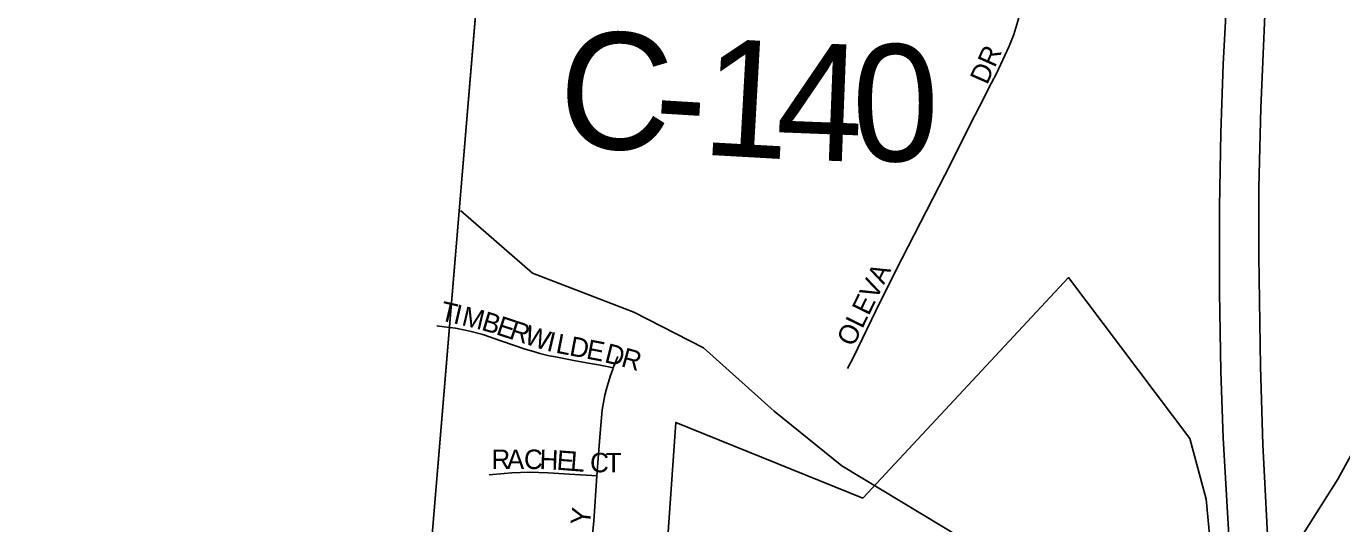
# Model space of a CAD drawing. Extents: x 1410790 to 1770854, y 448063 to 770588.
# Drawn here: x 1515012 to 1518387, y 615308 to 616585 of the extents above; entities that cross this region are included whole.
import ezdxf

# ---------------------------------------------------------------- set-up
doc = ezdxf.new("R2010")
doc.units = 0
for name, color, linetype in [('GM_X_Adjacent_County', 7, 'Continuous'), ('GM_X_Corporation', 7, 'Continuous'), ('GM_X_County', 7, 'Continuous'), ('GM_X_County_Road_Text', 7, 'Continuous'), ('GM_X_Interstate_Route', 7, 'Continuous'), ('GM_X_Minor_River', 7, 'Continuous'), ('GM_X_Township', 7, 'Continuous'), ('GM_X_Township_Subdivision', 7, 'Continuous'), ('GM_X_Township_Subdivision_Text', 7, 'Continuous')]:
    doc.layers.add(name, color=color, linetype=linetype)

msp = doc.modelspace()

# ---------------------------------------------------------------- linework, layer by layer
at = {"layer": 'GM_X_Adjacent_County'}
msp.add_lwpolyline([(1516461.1, 620230.1), (1516373.4, 619132.2), (1516259.6, 617762.4), (1516179.6, 616799.3), (1516178.5, 616785.8), (1516097.7, 615813.6), (1515954.1, 614086), (1515919.3, 613667.1), (1515731.8, 611411.8), (1515651.7, 611077.8), (1515518.3, 609565), (1515445.2, 608706.8), (1515408.7, 608098.4), (1515389.4, 607781.4), (1515371.9, 607595.9), (1515366.2, 607536), (1515338.7, 607244), (1515313.5, 606977), (1515267.7, 606491.6), (1515138.6, 605013.3), (1515011.7, 603538)], dxfattribs=at)
at = {"layer": 'GM_X_Corporation'}
msp.add_lwpolyline([(1516179.5, 616799.3), (1515953.4, 614078.9), (1516560, 613881.8), (1516677.9, 615567.6), (1517158.2, 615373.6), (1517686.1, 615939.7), (1517997.2, 615526.8), (1518038.9, 615370.3), (1518120.4, 614509.1), (1518162.4, 613531.2), (1518064.1, 613491.5), (1517980.9, 613509.2), (1517500.9, 613655.9), (1517499.1, 613630), (1517272.7, 613703.6), (1517210.9, 613723.6), (1517196.3, 613675.8), (1517284.6, 613626.9), (1518220.1, 613267.8), (1518169.3, 613029.1)], dxfattribs=at)
at = {"layer": 'GM_X_County'}
msp.add_lwpolyline([(1516461.1, 620230.1), (1516373.4, 619132.2), (1516259.6, 617762.4), (1516179.6, 616799.3), (1516178.5, 616785.8), (1516097.7, 615813.6), (1515954.1, 614086), (1515919.3, 613667.1), (1515731.8, 611411.8), (1515651.7, 611077.8), (1515518.3, 609565), (1515445.2, 608706.8), (1515408.7, 608098.4), (1515389.4, 607781.4), (1515371.9, 607595.9), (1515366.2, 607536), (1515338.7, 607244), (1515313.5, 606977), (1515267.7, 606491.6), (1515138.6, 605013.3), (1515011.7, 603538)], dxfattribs=at)
at = {"layer": 'GM_X_Interstate_Route'}
for points in [[(1518369.1, 611170.7), (1518352.1, 611439.2), (1518313.6, 612028.4), (1518281.4, 612490), (1518248.2, 612990.8), (1518240, 613108.7), (1518234, 613197), (1518223.3, 613372.3), (1518218.2, 613455.6), (1518188.2, 613894.3), (1518163, 614290.4), (1518139.7, 614644.1), (1518119.7, 614928.9), (1518097.8, 615262.7), (1518082.9, 615527.8), (1518077, 615698.1), (1518073.2, 615901.3), (1518073.1, 616120.9), (1518076.7, 616311), (1518082.9, 616487.8), (1518096.8, 616755.9)], [(1518478.2, 611056.4), (1518460.5, 611318.1), (1518429.3, 611763.2), (1518403, 612195.4), (1518389.4, 612391.7), (1518384.3, 612463.7), (1518353.9, 612908.8), (1518335.5, 613183.7), (1518325.6, 613340.9), (1518321.3, 613409.6), (1518275.5, 614090.4), (1518241.7, 614604.3), (1518213, 615019.9), (1518195.7, 615295), (1518184.5, 615511.4), (1518178.2, 615711.5), (1518174, 615993.7), (1518174.3, 616171), (1518178.9, 616374.6), (1518195.7, 616753.6)]]:
    msp.add_lwpolyline(points, dxfattribs=at)
at = {"layer": 'GM_X_Minor_River'}
for points in [[(1517975.9, 614867.7), (1518203.6, 615147.1), (1518377.1, 615422.3), (1518541.1, 615721.8), (1518584.2, 615777.1), (1518902.1, 615958.9), (1519075.7, 616129.7), (1519158.2, 616256.4), (1519264.5, 616370.5), (1519357.8, 616430.7), (1519412.2, 616447.6), (1519854, 616506.3), (1520047.6, 616574.3), (1520264, 616684)], [(1518568.9, 613289), (1518509.3, 613326.5), (1518484.3, 613381.2), (1518386.3, 613493.7), (1518369.5, 613560.2), (1518432.5, 613813.7), (1518418.9, 613940.4), (1518341, 614162.8), (1518345.2, 614275.1), (1518281.2, 614384.9), (1518226.6, 614568.7), (1518166.8, 614690.4), (1518054.1, 614765), (1517925.1, 614934.4), (1517873.5, 614955.6), (1517805.9, 614983.2), (1517689, 615049.9), (1517460.3, 615241.5), (1517103.9, 615456), (1516930.3, 615596.3), (1516749.2, 615758.8), (1516570.7, 615851), (1516310.2, 615951), (1516125.4, 616111.9)]]:
    msp.add_lwpolyline(points, dxfattribs=at)
at = {"layer": 'GM_X_Township'}
msp.add_lwpolyline([(1515651.7, 611077.8), (1515731.8, 611411.8), (1515919.3, 613667.1), (1515954.1, 614086), (1516097.7, 615813.6), (1516178.5, 616785.8), (1516179.6, 616799.3), (1516487.5, 616797.3), (1516773.1, 616795.4), (1517166.1, 616772.8), (1517456.2, 616756.2), (1517607.5, 616751.1), (1518142.2, 616733), (1518385.8, 616724.8), (1518670.6, 616715.2), (1522108.4, 616599.1), (1522130.9, 616592.7), (1524051.6, 616052.7), (1524353.6, 615961.7), (1525559.8, 615628.7)], dxfattribs=at)
at = {"layer": 'GM_X_Township_Subdivision'}
for points in [[(1517118.6, 615705.9), (1517134.2, 615735), (1517191.3, 615854.4), (1517226.4, 615925.1), (1517258.3, 615987.9), (1517306.3, 616080.7), (1517384.1, 616232.8), (1517412.9, 616291.6), (1517445.8, 616355.7), (1517457.7, 616379), (1517488, 616439.3), (1517501, 616463.9), (1517522.5, 616510), (1517533.5, 616533.9), (1517545.2, 616563.5), (1517553.5, 616589.4), (1517562.5, 616621.9), (1517576.2, 616675.6), (1517591.6, 616736.4), (1517600.9, 616772.9)], [(1516065.2, 615815.3), (1516084.2, 615813.1), (1516113.1, 615809.5), (1516137.8, 615804.7), (1516153.4, 615801), (1516182.7, 615793.1), (1516229.2, 615777.6), (1516291.4, 615756.2), (1516318.7, 615747.8), (1516329.7, 615744.9), (1516353.4, 615739.1), (1516365, 615736.6), (1516416.6, 615726.9), (1516448.8, 615720.9), (1516479.5, 615715.4), (1516505.4, 615710.1), (1516517.9, 615707.5)], [(1516475.8, 615430.9), (1516480.5, 615497.5), (1516483.8, 615540.1), (1516489.5, 615599.9), (1516492.3, 615619.2), (1516495.9, 615637.3), (1516500.4, 615654.1), (1516510.2, 615685.8), (1516516.8, 615704.6), (1516517.9, 615707.5)], [(1516517.9, 615707.5), (1516529.1, 615736.7)], [(1516199.1, 615433.3), (1516237.5, 615436.6), (1516257.2, 615438.2), (1516302.2, 615439.9), (1516351, 615438.4), (1516419.4, 615434.3), (1516462.4, 615431.7), (1516475.8, 615430.9)], [(1516362.2, 614946.9), (1516379.9, 614982.1), (1516399.3, 615026.9), (1516415.3, 615069.7), (1516428.8, 615109.9), (1516436.3, 615134.8), (1516447.7, 615181.8), (1516451.7, 615200.9), (1516459.7, 615246.3), (1516463.5, 615272.1), (1516467.6, 615314.3), (1516475.8, 615430.9)]]:
    msp.add_lwpolyline(points, dxfattribs=at)

# ---------------------------------------------------------------- texts
at = {"layer": 'GM_X_County_Road_Text'}
for s, rotation, p in [('C', 356.4461, (1516370.7, 616278.5)), ('1', 356.7903, (1516741.6, 616255.6)), ('4', 357.7752, (1516931.7, 616245)), ('0', 0.3695, (1517131.2, 616237.6)), ('-', 356.5261, (1516617.1, 616263.2))]:
    msp.add_text(s, height=300, rotation=rotation, dxfattribs=at).set_placement(p)
at = {"layer": 'GM_X_Township_Subdivision_Text'}
for s, rotation, p in [('DR', 66.0409, (1517476.9, 616432.6)), ('OLEVA', 63.9695, (1517133.8, 615759.7)), ('T', 346.9378, (1516070.8, 615830.7)), ('I', 346.9616, (1516105.1, 615822.8)), ('M', 346.6176, (1516126.5, 615817.8)), ('B', 343.2473, (1516177.1, 615805.8)), ('E', 341.7422, (1516214.7, 615794.5)), ('R', 341.6687, (1516248.1, 615783.5)), ('W', 342.4332, (1516286.3, 615770.8)), ('I', 346.6878, (1516344.7, 615752.5)), ('L', 348.9783, (1516368.2, 615747)), ('D', 349.2786, (1516403, 615740.2)), ('E', 349.2751, (1516446.3, 615732)), ('D', 345.9346, (1516493, 615723)), ('R', 344.1347, (1516535.3, 615712.4)), ('R', 359.9514, (1516205.1, 615448.2)), ('A', 359.9533, (1516244.7, 615448.2)), ('C', 359.9527, (1516288.7, 615448.1)), ('H', 357.8138, (1516327.8, 615448.1)), ('E', 355.6243, (1516371.3, 615446.5)), ('L', 355.5426, (1516406.3, 615443.8)), ('C', 358.9131, (1516457.8, 615440.2)), ('T', 359.9639, (1516498.4, 615439.4)), ('Y', 83.4241, (1516457.3, 615301.5))]:
    msp.add_text(s, height=50, rotation=rotation, dxfattribs=at).set_placement(p)

doc.saveas('drawing.dxf')
